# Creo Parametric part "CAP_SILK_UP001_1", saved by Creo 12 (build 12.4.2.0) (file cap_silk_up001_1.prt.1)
Units: Custom; MM, KILOGRAM, SECS

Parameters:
  PTC_WM_ITERATION = "0"
  PTC_WM_VERSION = "-.0"
  PTC_WM_LIFECYCLE_STATE = "In Work"
  PTC_WM_LIFECYCLE = "MO_CADDocument"
  PTC_WM_CREATED_BY = "Maximilian Roepper (Z0017RMS: MO)"
  PTC_WM_CREATED_ON = "18-Sep-26 11:36:42 AM"
  PTC_WM_MODIFIED_BY = "Maximilian Roepper (Z0017RMS: MO)"
  PTC_WM_MODIFIED_ON = "18-Sep-26 11:36:46 AM"
  PDMLINKNUMBER = "PDM000071455181"
  PTC_WM_NAME = "cap_silk_up001_1.prt"
  PTC_WM_NUMBER = "PDM000071455181"

Other parameters: WEIGHT, WEIGHT_FACTOR, WEIGHT_ADD, _MASS_TEMP, _DIFF_TEMP, MC_ERRORS, SUPPLIER

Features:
  1. coordinate system
  2. datum plane "PRT_YZ"
  3. datum plane "PRT_XY"
  4. datum plane "PRT_XZ"
  5. coordinate system
  6. datum axis
  7. datum axis
  8. datum axis
  9. coordinate system
  10. imported feature

Other named items: PRT, SIEMENS_MO, DRW_VIEW_ORG, PRT_X, PRT_Y, PRT_Z, CS0, ROUGH_GROB

Layers: 00_STD_CSYS-KSYS, 01_STD_PLANES-EBENEN, 02_STD_AXES-ACHSEN, 03_STD_CSYS-KSYS, 24_IMPORT_FEAT-IMPORT_KE

Surfaces: 10 plane, 4 cylinder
